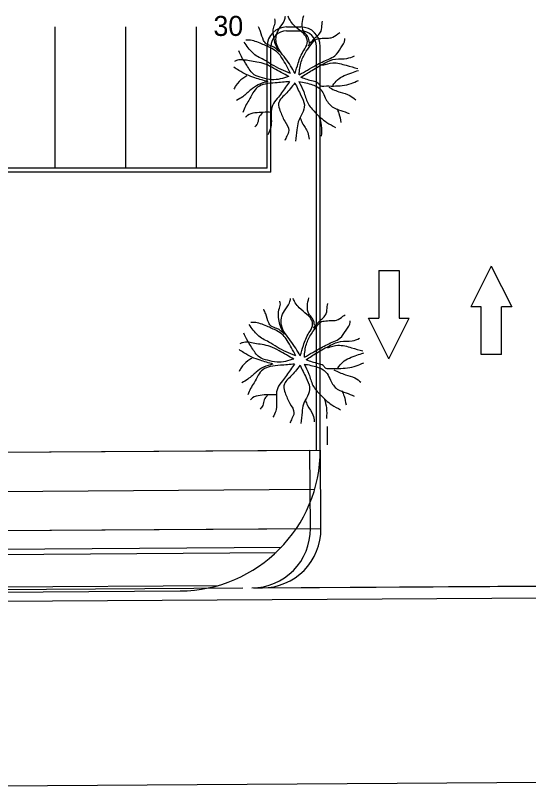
# Model space of a CAD drawing. Extents: x 6711323 to 6714641, y 1869258 to 1871224.
# Drawn here: x 6712862 to 6712927.4, y 1869589.4 to 1869688.5 of the extents above; entities that cross this region are included whole.
import ezdxf

# ---------------------------------------------------------------- set-up
doc = ezdxf.new("R2010")
doc.units = 0
for name, color, linetype in [('Curb Gutter (21)', 7, 'Continuous'), ('Front Align (17)', 7, 'Continuous'), ('Level 11', 7, 'Continuous'), ('Level 13', 7, 'Continuous'), ('Level 21', 7, 'Continuous'), ('Level 46', 7, 'Continuous'), ('Profile Grid (9)', 7, 'Continuous'), ('Ramp Anno (14)', 7, 'Continuous'), ('Undefined (Lv19)', 7, 'Continuous')]:
    doc.layers.add(name, color=color, linetype=linetype)

msp = doc.modelspace()

# ---------------------------------------------------------------- linework, layer by layer
at = {"layer": 'Curb Gutter (21)'}
for p, q in [((6712896.607, 1869687.072), (6712898.399, 1869687.072)), ((6712896.607, 1869686.572), (6712898.399, 1869686.572)), ((6712894.107, 1869669.072), (6712894.107, 1869684.572)), ((6712894.607, 1869668.572), (6712894.607, 1869684.572)), ((6712900.399, 1869633.23), (6712900.399, 1869684.572)), ((6712900.899, 1869633.23), (6712900.899, 1869684.572)), ((6712894.107, 1869669.072), (6712845.794, 1869669.072)), ((6712894.607, 1869668.572), (6712845.794, 1869668.572)), ((6712900.899, 1869633.759), (6712900.899, 1869636.08))]:
    msp.add_line(p, q, dxfattribs=at)
for centre, radius, start, end in [((6712896.607, 1869684.572), 2.5, 90, 180), ((6712896.607, 1869684.572), 2, 90, 180), ((6712898.399, 1869684.572), 2.5, 0, 90), ((6712898.399, 1869684.572), 2, 0, 90)]:
    msp.add_arc(centre, radius, start, end, dxfattribs=at)
at = {"layer": 'Front Align (17)'}
for p, q in [((6712867.107, 1869669.072), (6712867.107, 1869687.072)), ((6712876.107, 1869669.072), (6712876.107, 1869687.072)), ((6712885.107, 1869669.072), (6712885.107, 1869687.072))]:
    msp.add_line(p, q, dxfattribs=at)
at = {"layer": 'Level 11'}
for p, q in [((6712901.833, 1869633.855), (6712901.833, 1869636.177)), ((6712708.783, 1869631.94), (6712900.917, 1869633.181)), ((6712900.981, 1869623.172), (6712900.917, 1869633.181)), ((6712804.13, 1869622.556), (6712900.981, 1869623.181)), ((6712893.53, 1869615.624), (6712938.529, 1869615.914)), ((6712708.896, 1869614.44), (6712891.023, 1869615.616)), ((6712892.373, 1869615.616), (6712893.53, 1869615.624)), ((6712708.905, 1869612.941), (6712948.689, 1869614.489))]:
    msp.add_line(p, q, dxfattribs=at)
msp.add_arc((6712893.482, 1869623.124), 7.5, 270.36992, 0.36992, dxfattribs=at)
at = {"layer": 'Level 13'}
msp.add_line((6712709.057, 1869589.441), (6713820.204, 1869596.615), dxfattribs=at)
msp.add_arc((6712892.132, 1869623.124), 7.5, 270.36992, 0.36992, dxfattribs=at)
at = {"layer": 'Level 21'}
for p, q in [((6712708.783, 1869631.94), (6712899.567, 1869633.172)), ((6712899.631, 1869623.172), (6712899.567, 1869633.172)), ((6712804.13, 1869622.556), (6712899.631, 1869623.172)), ((6712892.18, 1869615.624), (6712937.179, 1869615.914)), ((6712708.896, 1869614.44), (6712891.023, 1869615.616)), ((6712708.905, 1869612.941), (6712948.689, 1869614.489))]:
    msp.add_line(p, q, dxfattribs=at)
at = {"layer": 'Level 46'}
for p, q in [((6712708.933, 1869626.81), (6712900.176, 1869628.178)), ((6712708.986, 1869619.477), (6712895.932, 1869620.814)), ((6712708.991, 1869618.81), (6712895.258, 1869620.143)), ((6712709.319, 1869614.791), (6712887.863, 1869615.928)), ((6712709.324, 1869614.124), (6712883.014, 1869615.23))]:
    msp.add_line(p, q, dxfattribs=at)
msp.add_arc((6712882.899, 1869633.23), 18, 270.36478, 0, dxfattribs=at)
at = {"layer": 'Profile Grid (9)'}
for points in [[(6712895.679, 1869683.909), (6712895.161, 1869684.929), (6712894.966, 1869685.768), (6712894.966, 1869687.027), (6712895.161, 1869687.747), (6712895.096, 1869688.107)], [(6712897.688, 1869681.151), (6712896.457, 1869683.07), (6712895.29, 1869685.049), (6712895.29, 1869685.948), (6712895.679, 1869686.907), (6712896.327, 1869687.927), (6712896.457, 1869688.466)], [(6712897.688, 1869681.151), (6712898.077, 1869682.471), (6712898.789, 1869684.089), (6712899.243, 1869684.989), (6712899.048, 1869685.888), (6712898.53, 1869686.428), (6712897.558, 1869687.267), (6712897.04, 1869687.927), (6712896.781, 1869688.466)], [(6712899.502, 1869685.049), (6712899.308, 1869685.828), (6712899.178, 1869686.008), (6712898.789, 1869686.488), (6712898.595, 1869687.507), (6712898.789, 1869688.526)], [(6712899.372, 1869684.689), (6712900.085, 1869685.528), (6712900.992, 1869686.548), (6712901.122, 1869687.447), (6712901.187, 1869687.807)], [(6712895.679, 1869683.909), (6712894.707, 1869684.629), (6712893.994, 1869684.929), (6712893.67, 1869685.349), (6712893.282, 1869686.488), (6712893.022, 1869687.087)], [(6712898.206, 1869680.972), (6712898.465, 1869682.65), (6712899.113, 1869683.97), (6712899.891, 1869685.049), (6712900.409, 1869685.528), (6712900.733, 1869685.588), (6712901.575, 1869685.648), (6712902.288, 1869685.708), (6712903.131, 1869686.188), (6712903.39, 1869686.368)], [(6712897.105, 1869681.151), (6712894.722, 1869682.267), (6712893.686, 1869682.905), (6712892.91, 1869683.305), (6712891.702, 1869684.422), (6712891.184, 1869685.141)], [(6712897.105, 1869681.151), (6712896.003, 1869683.13), (6712895.485, 1869683.79), (6712894.707, 1869684.329), (6712893.411, 1869684.929), (6712891.791, 1869685.408), (6712891.403, 1869685.408)], [(6712898.206, 1869680.972), (6712900.33, 1869682.187), (6712901.97, 1869682.985), (6712902.746, 1869683.384), (6712903.523, 1869684.422), (6712904.041, 1869685.46), (6712904.041, 1869685.62)], [(6712896.879, 1869680.749), (6712894.722, 1869680.35), (6712893.514, 1869680.59), (6712892.478, 1869680.989), (6712891.529, 1869682.187), (6712890.839, 1869683.305), (6712890.494, 1869684.023)], [(6712898.432, 1869680.67), (6712899.813, 1869681.548), (6712901.538, 1869682.506), (6712902.833, 1869682.985), (6712904.299, 1869683.065), (6712905.249, 1869683.384)], [(6712896.879, 1869680.749), (6712894.981, 1869681.787), (6712893.859, 1869682.346), (6712892.824, 1869682.586), (6712891.874, 1869682.746), (6712890.321, 1869682.825), (6712889.976, 1869682.666)], [(6712901.193, 1869682.187), (6712902.488, 1869682.506), (6712904.213, 1869682.187), (6712905.68, 1869681.787)], [(6712894.204, 1869680.111), (6712892.565, 1869680.59), (6712891.529, 1869680.989), (6712890.494, 1869681.548), (6712889.89, 1869681.947)], [(6712902.488, 1869679.632), (6712903.091, 1869680.35), (6712904.903, 1869681.229), (6712905.766, 1869681.548)], [(6712891.529, 1869680.829), (6712891.011, 1869680.51), (6712890.149, 1869679.632), (6712889.89, 1869679.153)], [(6712898.432, 1869680.67), (6712899.985, 1869680.191), (6712900.589, 1869679.951), (6712900.848, 1869679.632), (6712901.366, 1869679.552), (6712902.574, 1869679.552), (6712904.817, 1869679.871), (6712905.766, 1869680.27)], [(6712894.204, 1869680.111), (6712892.996, 1869679.711), (6712892.047, 1869679.073), (6712891.011, 1869678.194), (6712890.235, 1869677.715)], [(6712896.965, 1869680.111), (6712895.153, 1869679.951), (6712893.859, 1869679.791), (6712892.91, 1869679.392), (6712892.306, 1869678.673), (6712891.788, 1869677.715), (6712891.357, 1869676.997), (6712891.011, 1869676.198)], [(6712896.965, 1869680.111), (6712896.447, 1869679.392), (6712895.412, 1869677.955), (6712894.808, 1869677.077), (6712894.636, 1869676.039), (6712894.549, 1869674.122), (6712894.204, 1869673.324)], [(6712897.656, 1869679.951), (6712896.447, 1869678.514), (6712895.843, 1869677.875), (6712895.585, 1869677.316), (6712895.757, 1869676.438), (6712896.361, 1869675.08), (6712896.879, 1869673.883), (6712896.62, 1869673.164), (6712896.361, 1869672.605)], [(6712897.656, 1869679.951), (6712898.432, 1869678.354), (6712898.863, 1869677.156), (6712898.605, 1869676.039), (6712898.087, 1869675.001), (6712897.914, 1869673.963), (6712897.742, 1869672.526)], [(6712898.173, 1869680.111), (6712898.777, 1869678.833), (6712899.295, 1869677.396), (6712900.244, 1869676.198), (6712901.711, 1869674.921), (6712902.833, 1869674.282)], [(6712898.173, 1869680.111), (6712899.899, 1869679.711), (6712900.589, 1869679.392), (6712901.107, 1869678.913), (6712901.538, 1869678.035), (6712902.401, 1869676.917), (6712903.523, 1869676.438), (6712904.558, 1869676.039)], [(6712901.97, 1869679.392), (6712903.437, 1869678.753), (6712904.645, 1869678.354), (6712905.421, 1869677.795)], [(6712894.636, 1869676.198), (6712892.565, 1869676.118), (6712891.616, 1869675.799), (6712891.357, 1869675.56)], [(6712903.005, 1869676.677), (6712903.264, 1869676.039), (6712903.523, 1869674.921)], [(6712893.514, 1869676.118), (6712893.082, 1869675.56), (6712892.91, 1869674.841), (6712892.565, 1869674.362)], [(6712898.346, 1869675.48), (6712898.605, 1869674.841), (6712899.295, 1869673.643), (6712899.467, 1869672.765)], [(6712900.762, 1869675.639), (6712901.021, 1869674.522), (6712901.021, 1869673.164)], [(6712898.346, 1869645.179), (6712897.115, 1869647.097), (6712895.949, 1869649.076), (6712895.949, 1869649.975), (6712896.338, 1869650.935), (6712896.986, 1869651.954), (6712897.115, 1869652.494)], [(6712898.346, 1869645.179), (6712898.735, 1869646.498), (6712899.448, 1869648.117), (6712899.901, 1869649.016), (6712899.707, 1869649.915), (6712899.189, 1869650.455), (6712898.217, 1869651.294), (6712897.698, 1869651.954), (6712897.439, 1869652.494)], [(6712900.16, 1869649.076), (6712899.966, 1869649.855), (6712899.836, 1869650.035), (6712899.448, 1869650.515), (6712899.253, 1869651.534), (6712899.448, 1869652.554)], [(6712896.338, 1869647.937), (6712895.819, 1869648.956), (6712895.625, 1869649.795), (6712895.625, 1869651.055), (6712895.819, 1869651.774), (6712895.754, 1869652.134)], [(6712900.031, 1869648.716), (6712900.744, 1869649.556), (6712901.651, 1869650.575), (6712901.78, 1869651.474), (6712901.845, 1869651.834)], [(6712896.338, 1869647.937), (6712895.366, 1869648.656), (6712894.653, 1869648.956), (6712894.329, 1869649.376), (6712893.94, 1869650.515), (6712893.681, 1869651.115)], [(6712898.865, 1869644.999), (6712899.124, 1869646.678), (6712899.772, 1869647.997), (6712900.549, 1869649.076), (6712901.068, 1869649.556), (6712901.392, 1869649.616), (6712902.234, 1869649.676), (6712902.947, 1869649.736), (6712903.789, 1869650.215), (6712904.048, 1869650.395)], [(6712898.865, 1869644.999), (6712900.989, 1869646.214), (6712902.628, 1869647.012), (6712903.405, 1869647.412), (6712904.181, 1869648.45), (6712904.699, 1869649.488), (6712904.699, 1869649.647)], [(6712897.763, 1869645.179), (6712895.38, 1869646.294), (6712894.345, 1869646.932), (6712893.568, 1869647.332), (6712892.36, 1869648.45), (6712891.843, 1869649.168)], [(6712897.763, 1869645.179), (6712896.662, 1869647.157), (6712896.143, 1869647.817), (6712895.366, 1869648.357), (6712894.07, 1869648.956), (6712892.45, 1869649.436), (6712892.061, 1869649.436)], [(6712897.537, 1869644.777), (6712895.38, 1869644.377), (6712894.172, 1869644.617), (6712893.137, 1869645.016), (6712892.188, 1869646.214), (6712891.497, 1869647.332), (6712891.152, 1869648.05)], [(6712897.537, 1869644.777), (6712895.639, 1869645.815), (6712894.517, 1869646.374), (6712893.482, 1869646.613), (6712892.533, 1869646.773), (6712890.98, 1869646.853), (6712890.635, 1869646.693)], [(6712899.091, 1869644.697), (6712900.471, 1869645.575), (6712902.197, 1869646.533), (6712903.491, 1869647.012), (6712904.958, 1869647.092), (6712905.907, 1869647.412)], [(6712901.852, 1869646.214), (6712903.146, 1869646.533), (6712904.872, 1869646.214), (6712906.338, 1869645.815)], [(6712894.863, 1869644.138), (6712893.223, 1869644.617), (6712892.188, 1869645.016), (6712891.152, 1869645.575), (6712890.548, 1869645.974)], [(6712903.146, 1869643.659), (6712903.75, 1869644.377), (6712905.562, 1869645.256), (6712906.425, 1869645.575)], [(6712892.188, 1869644.857), (6712891.67, 1869644.537), (6712890.807, 1869643.659), (6712890.548, 1869643.18)], [(6712899.091, 1869644.697), (6712900.644, 1869644.218), (6712901.248, 1869643.978), (6712901.507, 1869643.659), (6712902.024, 1869643.579), (6712903.232, 1869643.579), (6712905.476, 1869643.898), (6712906.425, 1869644.298)], [(6712894.863, 1869644.138), (6712893.655, 1869643.739), (6712892.705, 1869643.1), (6712891.67, 1869642.222), (6712890.894, 1869641.743)], [(6712897.624, 1869644.138), (6712895.812, 1869643.978), (6712894.517, 1869643.819), (6712893.568, 1869643.419), (6712892.964, 1869642.701), (6712892.447, 1869641.743), (6712892.015, 1869641.024), (6712891.67, 1869640.226)], [(6712897.624, 1869644.138), (6712897.106, 1869643.419), (6712896.071, 1869641.982), (6712895.466, 1869641.104), (6712895.294, 1869640.066), (6712895.208, 1869638.15), (6712894.863, 1869637.351)], [(6712898.314, 1869643.978), (6712897.106, 1869642.541), (6712896.502, 1869641.902), (6712896.243, 1869641.343), (6712896.416, 1869640.465), (6712897.02, 1869639.108), (6712897.537, 1869637.91), (6712897.279, 1869637.192), (6712897.02, 1869636.633)], [(6712898.314, 1869643.978), (6712899.091, 1869642.381), (6712899.522, 1869641.184), (6712899.263, 1869640.066), (6712898.745, 1869639.028), (6712898.573, 1869637.99), (6712898.4, 1869636.553)], [(6712898.832, 1869644.138), (6712899.436, 1869642.86), (6712899.953, 1869641.423), (6712900.902, 1869640.226), (6712902.369, 1869638.948), (6712903.491, 1869638.309)], [(6712898.832, 1869644.138), (6712900.557, 1869643.739), (6712901.248, 1869643.419), (6712901.765, 1869642.94), (6712902.197, 1869642.062), (6712903.06, 1869640.944), (6712904.181, 1869640.465), (6712905.217, 1869640.066)], [(6712902.628, 1869643.419), (6712904.095, 1869642.781), (6712905.303, 1869642.381), (6712906.08, 1869641.822)], [(6712903.664, 1869640.705), (6712903.922, 1869640.066), (6712904.181, 1869638.948)], [(6712895.294, 1869640.226), (6712893.223, 1869640.146), (6712892.274, 1869639.826), (6712892.015, 1869639.587)], [(6712894.172, 1869640.146), (6712893.741, 1869639.587), (6712893.568, 1869638.868), (6712893.223, 1869638.389)], [(6712901.42, 1869639.667), (6712901.679, 1869638.549), (6712901.679, 1869637.192)], [(6712899.004, 1869639.507), (6712899.263, 1869638.868), (6712899.953, 1869637.671), (6712900.126, 1869636.792)]]:
    msp.add_spline(points, degree=3, dxfattribs=at)
at = {"layer": 'Undefined (Lv19)'}
for p, q in [((6712922.691, 1869656.624), (6712920.087, 1869651.419)), ((6712922.691, 1869656.624), (6712925.295, 1869651.419)), ((6712908.337, 1869656.057), (6712910.941, 1869656.057)), ((6712908.337, 1869656.057), (6712908.337, 1869649.989)), ((6712910.941, 1869656.057), (6712910.941, 1869649.989)), ((6712921.389, 1869651.419), (6712920.087, 1869651.419)), ((6712921.389, 1869645.351), (6712921.389, 1869651.419)), ((6712923.993, 1869645.351), (6712923.993, 1869651.419)), ((6712925.295, 1869651.419), (6712923.993, 1869651.419)), ((6712907.035, 1869649.989), (6712908.337, 1869649.989)), ((6712909.639, 1869644.784), (6712907.035, 1869649.989)), ((6712909.639, 1869644.784), (6712912.243, 1869649.989)), ((6712910.941, 1869649.989), (6712912.243, 1869649.989)), ((6712923.993, 1869645.351), (6712921.389, 1869645.351))]:
    msp.add_line(p, q, dxfattribs=at)

# ---------------------------------------------------------------- texts
at = {"layer": 'Ramp Anno (14)'}
msp.add_text('30', height=2.55, dxfattribs=at).set_placement((6712887.277, 1869685.93))

doc.saveas('drawing.dxf')
